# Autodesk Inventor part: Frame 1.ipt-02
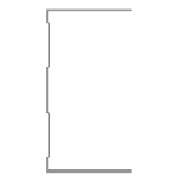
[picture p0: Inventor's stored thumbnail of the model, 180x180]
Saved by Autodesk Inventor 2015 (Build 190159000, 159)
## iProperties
IsCustomPart: 1
Created: 2015-04
Part Number: Frame 1.ipt-02
Material: Aluminum 6061
Description: Kévin Novo
Document SubType Name: Modeling
Standard: Kevin
Designer: suporte
Standards Organization: Kevin
Language: en-US
Size Designation: (Unnamed 2)
Categories: <MemberInstance><Categories><Category DisplayName="Structural Shapes" InternalName="089c4875-fa83-4c05-b084-43b9cc11f5ed" Mnemonic="GRDR"><CategoryParameter Dis
Density: 2.7 g/cm^3
Appearance: Aluminum - Flat
_CCFamilyMember: 2
_CCFamilyDisplayName: Kévin - Kévin Novo
_FrameMemberDoc: Frame Member File
_Version: 15.0.0
_GetPNFromCC: 1
G_W: 50,000 mm
G_H: 75,000 mm
G_L: 470,645 mm
+BD433694-75ED-40FA-B604-0D23CBD579F9+CUTDETAIL3: Miter 67,49 deg
+5C76CBEB-8B41-4733-85A3-2AE3D2FC03BA+CUTDETAIL4: Miter 67,51 deg
Author: suporte
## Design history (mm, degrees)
node "Start Plane"
node "End Plane"
sketch "Sketch"
  geometry: L1 (24.7, 37.5)-(24.7, 36.9); L2 (24.7, 36.9)-(-24.7, 36.9); L3 (-24.7, -36.9)-(24.7, -36.9); L4 (24.7, -36.9)-(24.7, -37.5); L5 (24.7, -37.5)-(-25.3, -37.5); L6 (-25.3, 37.5)-(24.7, 37.5); L7 (-24.7, 36.9)-(-24.7, 31.9); L8 (-24.7, 31.9)-(-23.3, 30.5); L9 (-23.3, 30.5)-(-23.3, 10.934); L10 (-23.3, 10.934)-(-24.7, 9.534); L11 (-24.7, 9.534)-(-24.7, -9.534); L12 (-24.7, -9.534)-(-23.3, -10.934); L13 (-23.3, -10.934)-(-23.3, -30.5); L14 (-23.3, -30.5)-(-24.7, -31.9); L15 (-24.7, -31.9)-(-24.7, -36.9); L16 (-25.3, -37.5)-(-25.3, -31.651); L17 (-25.3, -31.651)-(-23.9, -30.251); L18 (-23.9, -30.251)-(-23.9, -11.183); L19 (-23.9, -11.183)-(-25.3, -9.783); L20 (-25.3, -9.783)-(-25.3, 9.783); L21 (-25.3, 9.783)-(-23.9, 11.183); L22 (-23.9, 11.183)-(-23.9, 30.251); L23 (-23.9, 30.251)-(-25.3, 31.651); L24 (-25.3, 31.651)-(-25.3, 37.5); L25 (-25.3, 0)-(30.37, 0); 3 further points
  constraints: 50 end point, 10 point on line, 9 parallel, 5 perpendicular, 4 equal length, 3 midpoint, 3 vertical, 2 vertical alignment, 1 collinear, 1 horizontal, 1 horizontal alignment
  dimensions: "d3" = 0.6 distance of L1.start L1.end (= d6); "d5" = 75 distance between parallel lines of L5 L6; "d6" = 0.6 distance between parallel lines of L24 L7 (= d8); "d7" = 0.6 distance between parallel lines of L8 L23 (= d8); "d8" = 0.6 distance between parallel lines of L22 L9 (= d12); "Espessura" = 0.6 distance between parallel lines of L17 L14; "d10" = 0.6 distance between parallel lines of L13 L18 (= Espessura); "d11" = 0.6 distance between parallel lines of L12 L19 (= Espessura); "d12" = 0.6 distance between parallel lines of L21 L10 (= d11); "d13" = 5 distance of L2.end L7.end; "d15" = 135 deg angle of L9 L8; "d16" = 2 distance between parallel lines of L24 L9; "d17" = 50 distance of L6.start L1.start
extrude "Body" join sketch "Sketch" stored distance "d24" = 0.13; taper "d25" = 0 deg
node "Driven Length"
  sketch "Sketch10"
    geometry: L1 (0, 0)-(10, 0) reference
    constraints: 2 end point, 1 horizontal
  workplane "Work Plane7"
  sketch "Sketch11"
    geometry: L1 (-2, 5.175)-(12, 5.175) reference; L2 (-2, 475.82)-(12, 475.82) reference
    dimensions: "d27" = 470.64466 distance between parallel lines of L1 L2 (derived)
workplane "Work Plane10"
split "Split3"
workplane "Work Plane11"
split "Split4"
body "Solid1"
other parameters: "tamanho" = 481, "G_OFFSET_START" = -5.17512 [user parameter; used in 1 equation term], "G_OFFSET_END" = -5.18022 [user parameter; used in 1 equation term], "d22" = 5.17512 (= -G_OFFSET_START), "d23" = 475.81978 (= tamanho + G_OFFSET_END), "G_L" = 470.64466 (= d27) [user parameter], "d34" = 90 deg
